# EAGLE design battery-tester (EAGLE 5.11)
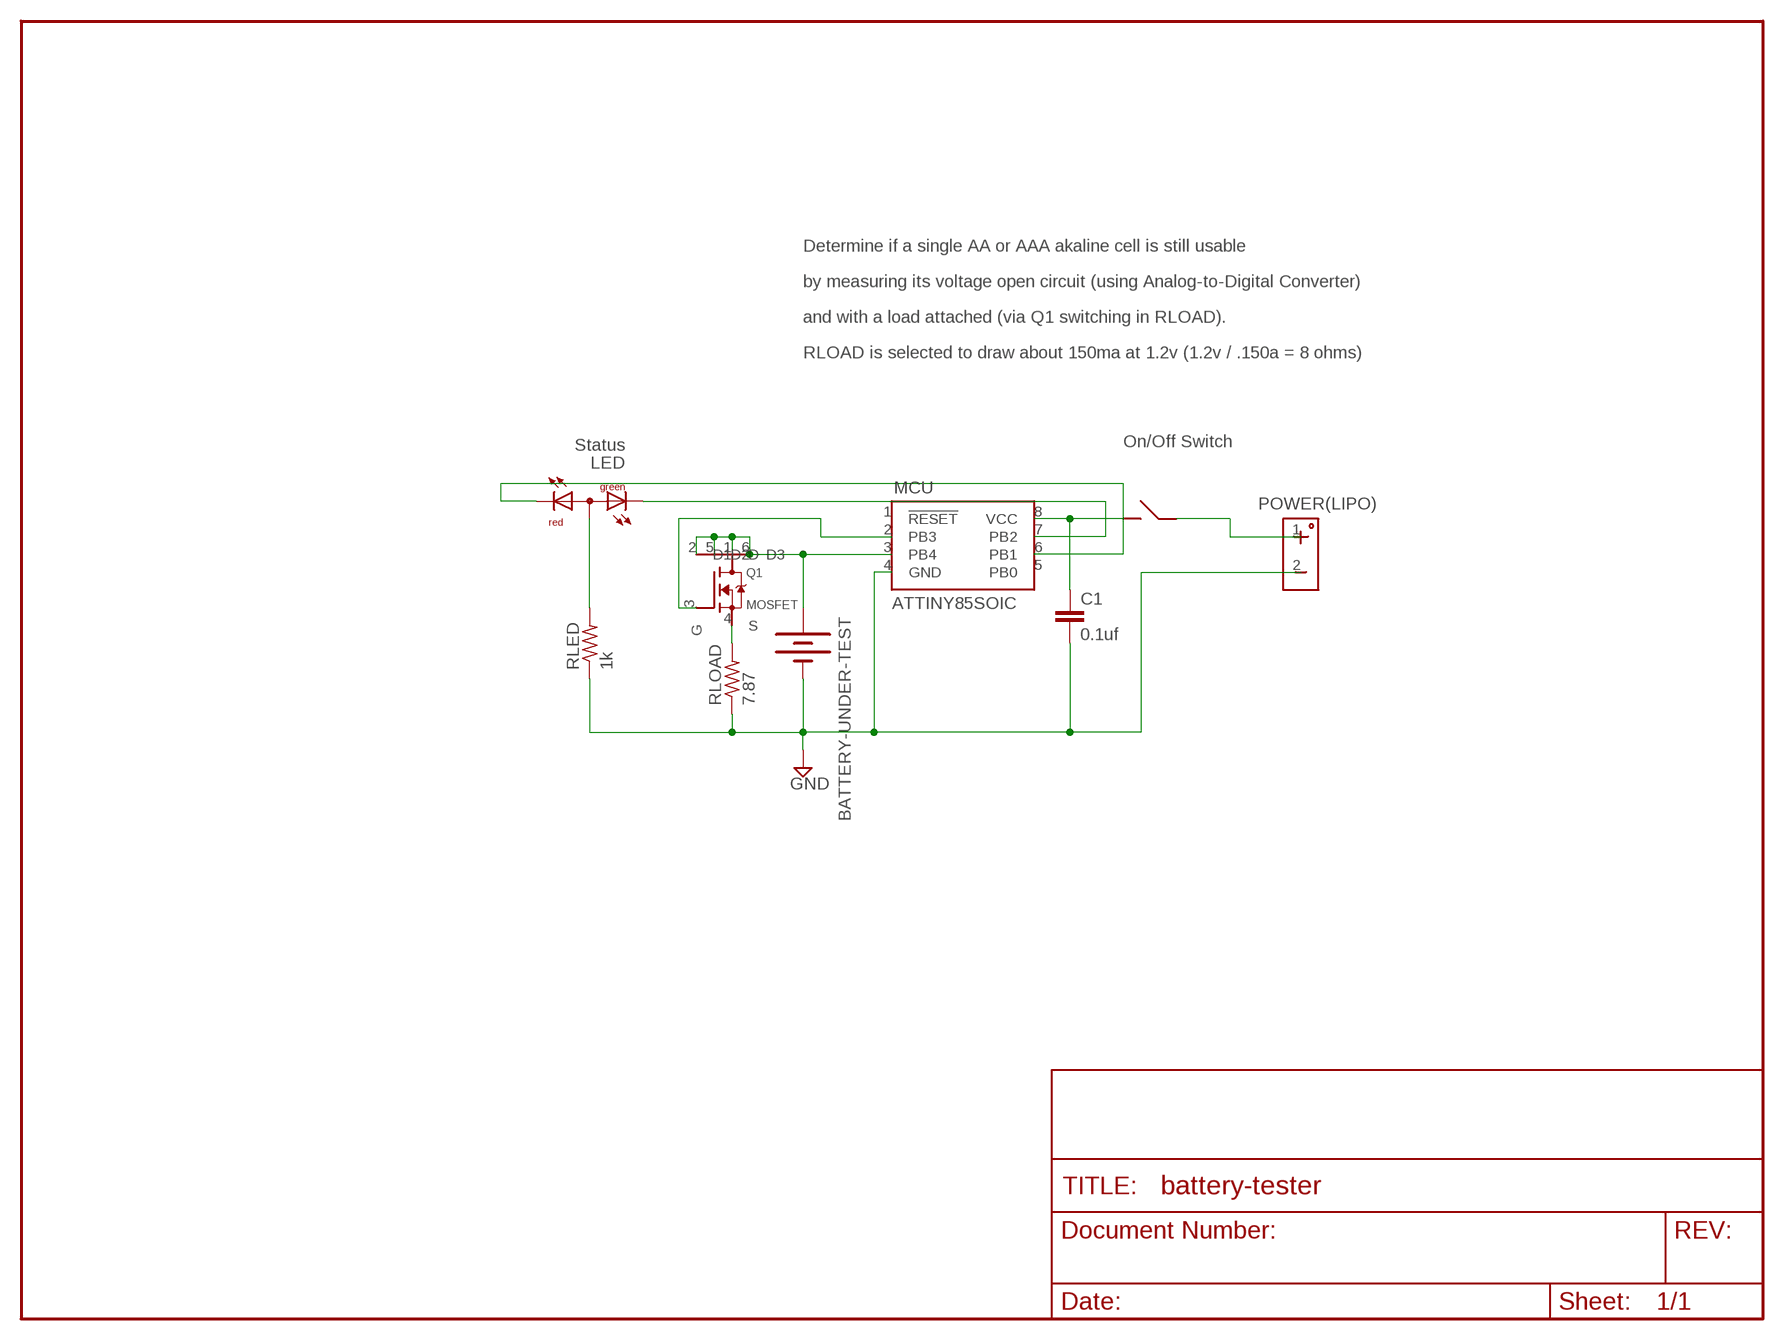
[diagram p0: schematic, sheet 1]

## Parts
BATTERY-UNDER-TEST  BATTERYAA  [BATTERY-AA]
C1  0.1uf  C-EUC0805  [C0805]
LED  Status  DUOLED-RG-A  [DUOLED-A-5MM]
MCU  ATTINY85SOIC  [8SOIC]
ON-OFF-SWITCH  ON-OFF-SWITCH  PUSH-BUTTON-SWITCH  [2SIL]
POWER(LIPO)  HEADER-POWER  [HEADER-POWER]
Q1  MOSFET  MOSFET-551  [SC89-6]
RLED  1k  R-US_R1206  [R1206]
RLOAD  7.87  R-US_R0805  [R0805]

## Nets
GND: BATTERY-UNDER-TEST.GND@1(-) C1.2 MCU.4(GND) POWER(LIPO).2 RLED.1 RLOAD.1
N$1: Q1.4(S) RLOAD.2
N$2: LED.CX(CG) MCU.7(PB2)
N$4: BATTERY-UNDER-TEST.PWR@1(+) MCU.3(PB4) Q1.1(D) Q1.2(D1) Q1.5(D2) Q1.6(D3)
N$5: ON-OFF-SWITCH.NO POWER(LIPO).1
N$6: LED.CR MCU.6(PB1)
N$7: LED.A RLED.2
N$8: C1.1 MCU.8(VCC) ON-OFF-SWITCH.COM
N$9: MCU.2(PB3) Q1.3(G)
Unconnected: MCU.1(!RESET) MCU.5(PB0)

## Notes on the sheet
- Determine if a single AA or AAA akaline cell is still usable
- by measuring its voltage open circuit (using Analog-to-Digital Converter)
- and with a load attached (via Q1 switching in RLOAD).
- RLOAD is selected to draw about 150ma at 1.2v (1.2v / .150a = 8 ohms)
- On/Off Switch

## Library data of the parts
BATTERY-UNDER-TEST = SparkFun:BATTERY: Battery Holders
C1 = rcl:C-EU: CAPACITOR, European symbol
LED = led:DUOLED-RG-A: DUO LED 2 colors (red/green), 5 mm, round, common Anode www.ligitek.com or other producers.
MCU = trl:ATTINY85
ON-OFF-SWITCH = trl:PUSH-BUTTON-SWITCH
POWER(LIPO) = trl:HEADER-POWER
Q1 = trl:MOSFET-551
RLED RLOAD = resistor:R-US_: RESISTOR, American symbol

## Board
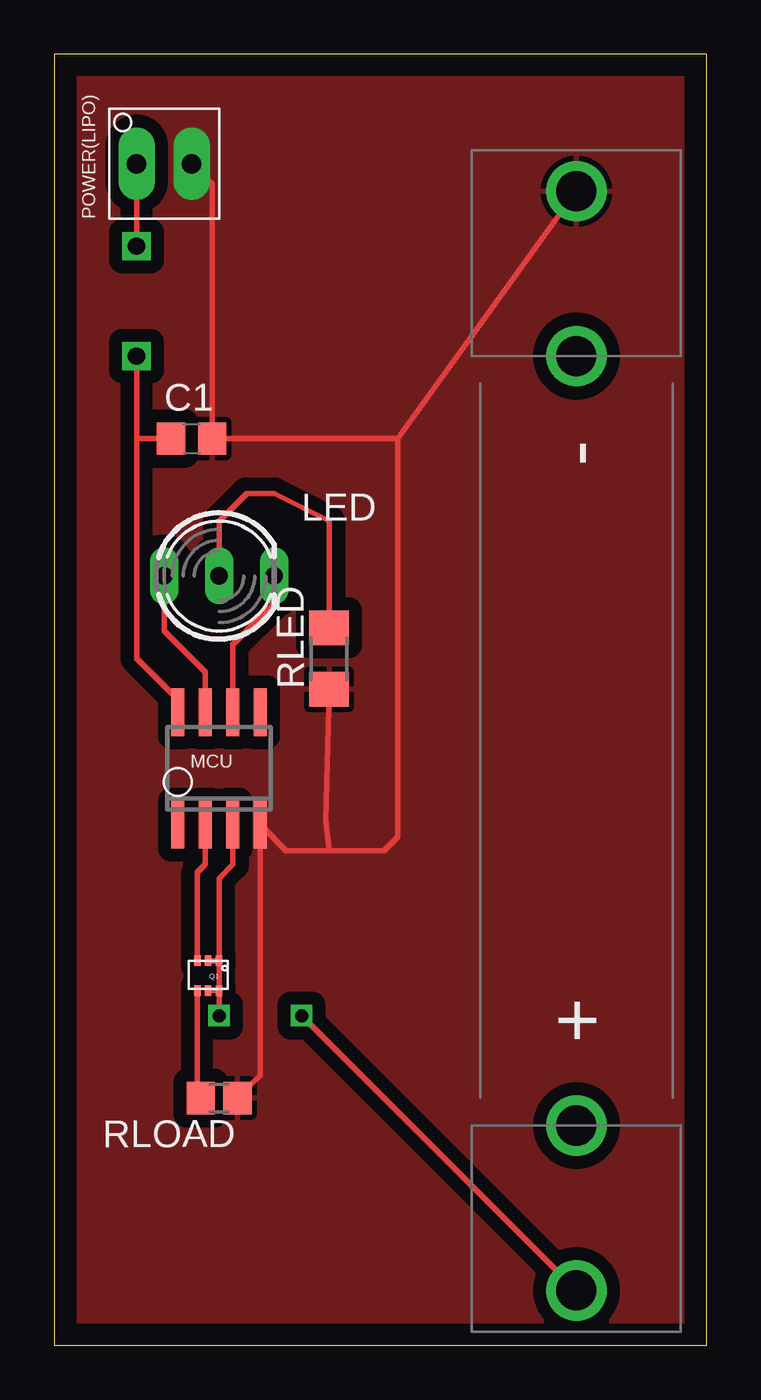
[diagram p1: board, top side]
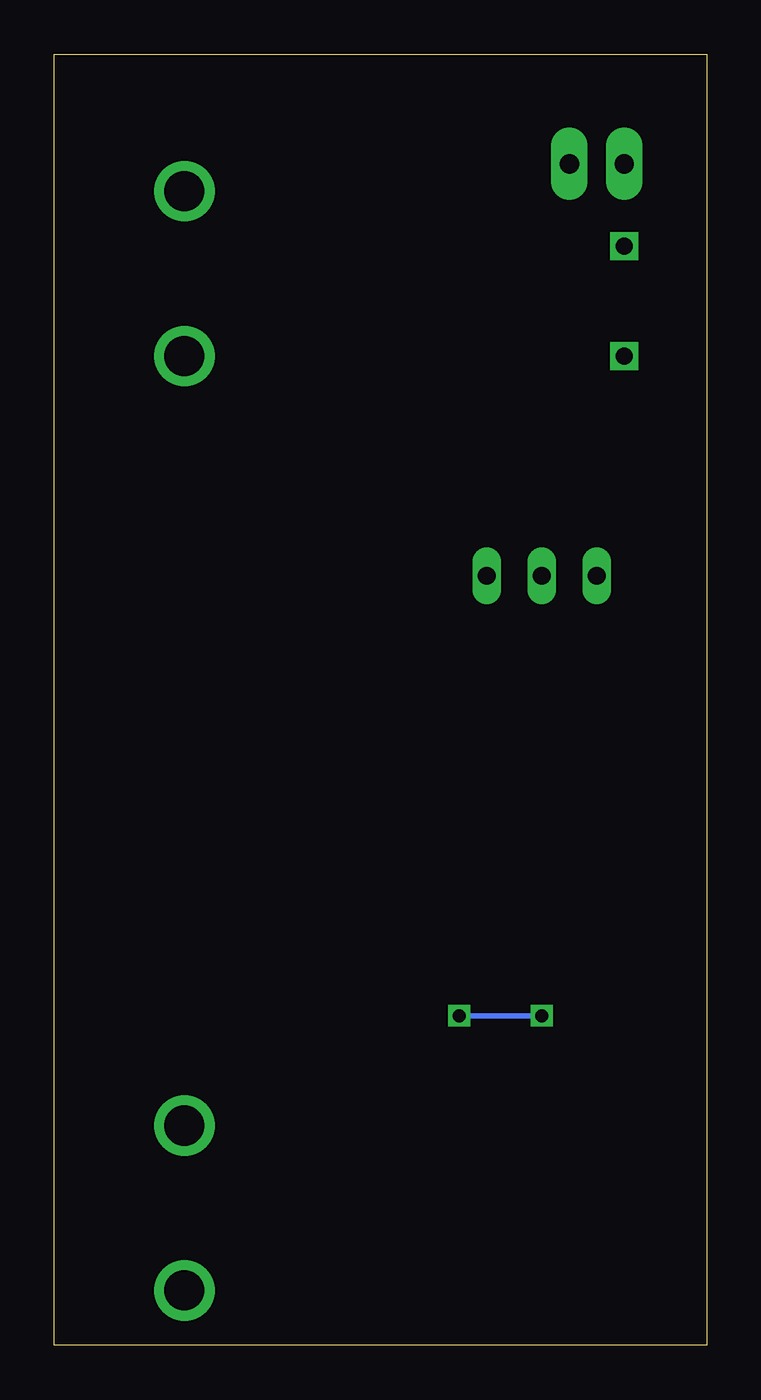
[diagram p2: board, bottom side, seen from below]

Size 30.15 x 59.68 mm. Coordinates in mm from the lower left corner, seen from the top.
Outline: 0,0 30.15,0 30.15,59.68 0,59.68 0,0
Copper layers (1*16): Top 0.035mm / dielectric 1.5mm / Bottom 0.035mm
Design rules "default": minimum track width 10mil, minimum drill 0.6mm, track to track 8mil, track to pad 8mil, pad to pad 8mil, via to via 8mil, smd to smd 8mil, copper to edge 40mil, drill to drill 8mil, minimum pad ring 10mil, minimum via ring 8mil, stop-mask expansion 4mil, vias tented up to drill 0mil, thermal gap 10mil

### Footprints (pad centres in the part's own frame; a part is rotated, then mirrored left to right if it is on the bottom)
BATTERY-AA = drill 1.854 round: GND@1 25.4,0; GND@2 17.78,0; PWR@1 -25.4,0; PWR@2 -17.78,0
C0805 = smd 1.3 x 1.5: 1 -0.95,0; 2 0.95,0
DUOLED-A-5MM = drill 0.813 long: A 0,0; CR 2.54,0; CX -2.54,0
8SOIC = smd 0.6 x 2.2: 1 -1.905,-2.6; 2 -0.635,-2.6; 3 0.635,-2.6; 4 1.905,-2.6; 5 1.905,2.6; 6 0.635,2.6; 7 -0.635,2.6; 8 -1.905,2.6
2SIL = drill 0.8 square: COM 0,2.54; NO 0,-2.54
HEADER-POWER = drill 0.9 pad 1.676 long: 1 0,1.27; 2 0,-1.27
SC89-6 = smd 0.3 x 0.478: 1 0,0; 2 0.501,0; 3 1.002,0; 4 1.002,1.38; 5 0.501,1.38; 6 0,1.38
R1206 = smd 1.6 x 1.803: 1 -1.422,0; 2 1.422,0
R0805 = smd 1.3 x 1.5: 1 -0.85,0; 2 0.85,0

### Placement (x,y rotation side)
BATTERY-UNDER-TEST  24.13,27.94 90 top
C1  6.35,41.91 0 top
LED  7.62,35.56 0 top
MCU  7.62,26.67 0 top
ON-OFF-SWITCH  3.81,48.26 180 top
POWER(LIPO)  5.08,54.61 90 top
Q1  7.62,17.78 180 top
RLED  12.7,31.75 90 top
RLOAD  7.62,11.43 180 top

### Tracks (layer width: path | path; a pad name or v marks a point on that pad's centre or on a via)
GND
  Top 0.254: RLOAD.1 9.53,12.48 MCU.4 10.73,22.86 12.7,22.86 | 15.88,41.91 BATTERY-UNDER-TEST.GND@1 | 15.88,41.91 C1.2 7.3,53.66 POWER(LIPO).2 | 12.7,22.86 15.24,22.86 15.88,23.5 15.88,41.91 | RLED.1 12.55,24.28 12.7,22.86
  pour Top (isolate 0.61): 0,59.69 29.21,59.69 29.21,0 0,0
N$1
  Top 0.254: Q1.4 6.62,11.58 RLOAD.2
N$2
  Top 0.254: MCU.7 6.99,31.11 5.08,33.02 LED.CX
N$4  (via drill 0.6)
  Top 0.254: Q1.1 Q1.2 | Q1.6 Q1.5 | Q1.6 Q1.1 | Q1.1 7.62,21.59 8.26,22.23 MCU.3 | BATTERY-UNDER-TEST.PWR@1 v11.43,15.24 | v7.62,15.24 Q1.6
  Bottom 0.254: v11.43,15.24 v7.62,15.24
N$5
  Top 0.254: ON-OFF-SWITCH.NO POWER(LIPO).1
N$6
  Top 0.254: MCU.6 8.26,32.38 10.16,34.29 LED.CR
N$7
  Top 0.254: LED.A 7.62,38.1 8.89,39.37 10.16,39.37 12.7,38.1 RLED.2
N$8
  Top 0.254: MCU.8 5.71,29.84 3.81,31.75 3.81,41.91 | 3.81,41.91 ON-OFF-SWITCH.COM | 3.81,41.91 C1.1
N$9
  Top 0.254: Q1.3 6.62,21.86 6.99,22.23 MCU.2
